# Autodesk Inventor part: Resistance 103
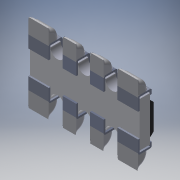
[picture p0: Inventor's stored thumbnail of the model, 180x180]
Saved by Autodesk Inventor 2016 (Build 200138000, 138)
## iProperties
Created: 2018-03
Part Number: Resistance 103
Material: Générique
Document SubType Name: Modeling
Designer: Bruno
Density: 1 g/cm^3
Appearance: Par défaut
Author: Bruno
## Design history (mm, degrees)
feature "Composite1"
body "Srf1"
